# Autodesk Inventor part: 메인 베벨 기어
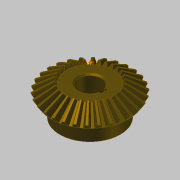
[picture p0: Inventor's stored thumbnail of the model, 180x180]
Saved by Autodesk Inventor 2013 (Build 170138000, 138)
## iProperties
Created: 2016-04
Part Number: 메인 베벨 기어
Material: 강철, 탄소
Document SubType Name: Modeling
Designer: mdu
Categories: <?xml version="1.0" encoding="UTF-16"?> <MemberInstance><Categories><FamilyTemplate><FamilyTemplateParameter ValueType="xs:double" Id="1" ObjectReferenceKey="da
Mass: 269.926 g
Surface Area: 108.837 cm^2
Volume: 34.2981 cm^3
Density: 7.87 g/cm^3
CustomPartVersion: 1
Author: mdu
Revision Number: 1
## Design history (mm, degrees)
node "맨 위 점"
node "메쉬 평면2"
sketch "톱니 본체 스케치"
  geometry: L1 (0, 0)-(28.669, -21.997); L2 (28.669, -21.997)-(31.109, -18.336); L3 (31.109, -18.336)-(0, 0); L4 (30, -20)-(0, 0); L5 (17.219, -13.212)-(18.685, -11.013); L6 (28.669, -21.997)-(17.219, -13.212); L7 (31.109, -18.336)-(18.685, -11.013); L8 (0, -39.387)-(0, 6.564) reference; L9 (0, -20)-(31.109, -20)
  constraints: 16 end point, 4 point on line, 3 perpendicular, 2 collinear, 1 horizontal alignment, 1 vertical alignment
  dimensions: "d0" = 60 diameter of L4.start L8 (= da_de); "d1" = 57.33744 diameter of L1.end L8 (= da_dfe); "d2" = 62.2188 diameter of L2.end L8 (= da_dae); "d3" = 14.4 distance between parallel lines of L2 L5 (= da_b); "d4" = 18.3359 vertical distance of L2.end L1.start (= da_ve)
revolve "톱니 본체" sketch "톱니 본체 스케치" stored, may be unused: angle "d5" = 90 deg
node "시작점"
node "톱니 평면"
sketch "시작 스케치"
  geometry: L1 (0, -23.505)-(0, 10.645) reference; L2 (-0.709, -2.928)-(0.709, -2.928); A1 r 19.188 centre (-19.457, -7.014) between (-0.709, -2.928) and (-3.232, 3.229); A2 r 19.188 centre (19.457, -7.014) between (3.232, 3.229) and (0.709, -2.928); A3 r 57.403 centre (0, -54.083) between (3.232, 3.229) and (-3.232, 3.229); 1 further point
  constraints: 6 point on circle, 3 centre point, 3 symmetric about line, 2 end point, 1 coincident, 1 perpendicular, 1 other
  dimensions: "d7" = 19.18795 radius of A1 (= fd_rr); "d8" = 19.45712 horizontal distance of point (0, -54.083) A1.centre (= fd_x); "d9" = 47.06905 vertical distance of point (0, -54.083) A1.centre (= fd_y); "d57" = 57.40327 radius of A3 (= 0.5 x fd_dva + 0.3 x da_he); "d58" = 51.15527 distance from line of A3.centre L2 (= 0.5 x fd_dva - 1.12 x da_he)
node "끝점"
  node "끝 평면"
sketch "3D 스케치 오른쪽"
  node "Helical Curve Right" dims "d65" = 229.90621 (computed from da_dm, da_delta, da_beta), "d66" = 31.5, "d67" = 60 (= da_de), "d68" = -9.82794 (= -da_delta), "d69" = 8.10972 (computed from fd_loft, da_delta)
node "끝 평면 오른쪽"
sketch "끝 스케치 오른쪽"
  geometry: L1 (0, -41.54)-(0, 13.178) reference; L2 (-0.422, -1.69)-(0.422, -1.69); A1 r 11.427 centre (-11.587, -4.123) between (-0.422, -1.69) and (-1.925, 1.977); A2 r 11.427 centre (11.587, -4.123) between (1.925, 1.977) and (0.422, -1.69); A3 r 34.184 centre (0, -32.153) between (1.925, 1.977) and (-1.925, 1.977); 1 further point
  constraints: 6 point on circle, 3 centre point, 3 symmetric about line, 2 end point, 1 coincident, 1 perpendicular, 1 other
  dimensions: "d70" = 11.58699 horizontal distance of A3.centre A1.centre (computed from fd_x, fd_ratio); "d71" = 28.03028 vertical distance of point (0, -32.153) A1.centre (computed from fd_y, fd_ratio); "d72" = 11.4267 radius of A1 (computed from fd_rr, fd_ratio); "d73" = 30.46369 distance from line of point (0, -32.153) L2 (computed from d58, fd_ratio); "d74" = 34.18446 radius of A3 (computed from d57, fd_ratio)
feature "로프트 오른쪽" sketch "끝 스케치 오른쪽" dims "d75" = 0, "d77" = 0, "d79" = 0, "d80" = 90 deg, "d85" = 20, "d92" = 90 deg, "d93" = 90 deg, "da_teethtype" = 0 [user parameter]
sketch "3D 스케치 왼쪽"
  node "Helical Curve Left" dims "d26" = 229.90621 (computed from da_dm, da_delta, da_beta), "d27" = 8.10972 (computed from fd_loft, da_delta), "d28" = 60 (= da_de), "d29" = -9.82794 (= -da_delta)
node "끝 평면 왼쪽"
sketch "끝 스케치 왼쪽" dims "d56" = 10.3728 (derived)
  geometry: L1 (0, -43.753)-(0, 15.405) reference; L2 (-0.422, -1.678)-(0.422, -1.678); A1 r 11.427 centre (-11.587, -4.111) between (-0.422, -1.678) and (-1.925, 1.988); A2 r 11.427 centre (11.587, -4.111) between (1.925, 1.988) and (0.422, -1.678); A3 r 34.184 centre (0, -32.142) between (1.925, 1.988) and (-1.925, 1.988); 2 further points; 1 other entity
  constraints: 6 point on circle, 3 centre point, 3 symmetric about line, 2 end point, 1 coincident, 2 other
  dimensions: "d30" = 11.4267 radius of A1 (computed from fd_rr, fd_ratio); "d31" = 11.58699 horizontal distance of point (0, -32.142) A1.centre (computed from fd_x, fd_ratio); "d32" = 28.03028 vertical distance of A1.centre point (0, -32.142) (computed from fd_y, fd_ratio); "d61" = 34.18446 radius of A3 (computed from d57, fd_ratio); "d62" = 30.46369 distance from line of point (0, -32.142) L2 (computed from d58, fd_ratio)
feature "로프트 왼쪽" sketch "끝 스케치 왼쪽" dims "d35" = 0, "d37" = 0, "d39" = 0, "d40" = 90 deg, "d84" = 10, "d90" = 90 deg, "d91" = 90 deg, "da_teethtype" = 0 [user parameter]
sketch "본체 스케치"
  geometry: L1 (0, -35.038)-(0, -19.531) reference; L2 (28.669, -21.997)-(17.219, -13.212) reference; L3 (17.219, -13.212)-(0, -13.212); L4 (28.669, -21.997)-(0, -21.997)
  constraints: 4 end point, 2 perpendicular, 2 point on line
revolve "본체 고정" sketch "본체 스케치" stored, may be unused: angle "d46" = 90 deg
feature "피치 지름" dims angle "d47" = 90 deg
sketch "스케치8"
  geometry: C1 r 22.5 at (0, 0); 1 further point
  constraints: 1 centre point, 1 coincident
  dimensions: "d94" = 45 diameter of C1
extrude "돌출1" join sketch "스케치8" distance "d95" = 13; taper "d96" = 0 deg
sketch "스케치9"
  geometry: 1 further point
hole "구멍1" sketch "스케치9" at (0, 0) diameter "d97" = 17; stored, may be unused: countersink angle "d101" = 90 deg, drill point angle "d103" = 118 deg; dims "d98" = 6, "d99" = 4, "d100" = 2, "d102" = 8
sketch "스케치10"
  geometry: L1 (8.124, 2.5)-(10.8, 2.5); L2 (10.8, 2.5)-(10.8, -2.5); L3 (10.8, -2.5)-(8.124, -2.5); A1 r 8.5 centre (0, 0) between (8.124, 2.5) and (8.124, -2.5) reference; 1 further point
  constraints: 6 end point, 2 parallel, 2 point on circle, 1 horizontal, 1 perpendicular
  dimensions: "d104" = 5 distance of L1.end L2.end; "d112" = 19.3 dimension on A1 L2
extrude "돌출2" cut sketch "스케치10" stored distance "d106" = 10; taper "d107" = 0 deg
chamfer "모따기1" distance "d108" = 1; stored, may be unused: second distance "d109" = 2, angle "d110" = 45 deg
fillet "모깎기1" dims "d111" = 2
body "Solid1"
feature "로프트" dims "d17" = 0, "d18" = 90 deg, "d19" = 0, "d20" = 90 deg, "d89" = 0, "da_teethtype" = 0 [user parameter]
pattern_circular "원형 패턴" dims angle "d22" = 360 deg, "d88" = 0, "da_teethtype" = 0 [user parameter]
pattern_circular "원형 패턴 오른쪽" dims angle "d82" = 360 deg, "da_teethtype" = 0 [user parameter]
pattern_circular "원형 패턴 왼쪽" dims angle "d42" = 360 deg, "da_teethtype" = 0 [user parameter]
sketch "끝 스케치"
  geometry: L1 (0, -15.359)-(0, 6.983) reference; L2 (-0.422, -1.69)-(0.422, -1.69); A1 r 11.427 centre (-11.587, -4.123) between (-0.422, -1.69) and (-1.925, 1.977); A2 r 11.427 centre (11.587, -4.123) between (1.925, 1.977) and (0.422, -1.69); A3 r 34.184 centre (0, -32.153) between (1.925, 1.977) and (-1.925, 1.977); 1 further point
  constraints: 6 point on circle, 3 centre point, 3 symmetric about line, 2 end point, 1 coincident, 1 other
  dimensions: "d12" = 11.4267 radius of A1 (computed from fd_rr, fd_ratio); "d15" = 11.58699 horizontal distance of A1.centre point (0, -32.153) (computed from fd_x, fd_ratio); "d16" = 28.03028 vertical distance of A1.centre point (0, -32.153) (computed from fd_y, fd_ratio); "d59" = 34.18446 radius of A3 (computed from d57, fd_ratio); "d60" = 30.46369 distance from line of A3.centre L2 (computed from d58, fd_ratio)
sketch "Sketch6"
  geometry: L1 (30, -20)-(0, 0) reference; L2 (0, -37.8)-(0, 6.3) reference
body "Srf1"
other parameters: "da_b" = 14.4 [user parameter; used in 2 equation terms], "da_de" = 60 [user parameter; used in 4 equation terms], "da_dae" = 62.2188 [user parameter; used in 2 equation terms], "da_dfe" = 57.33744 [user parameter; used in 1 equation term], "da_le" = 36.05551 [user parameter; used in 1 equation term], "da_omega" = 90 deg [user parameter; used in 1 equation term], "da_beta" = 0 [user parameter; used in 2 equation terms], "da_delta" = 9.82794 [user parameter; used in 8 equation terms], "da_alpha" = 20 deg [user parameter; used in 2 equation terms], "da_he" = 4.4 [user parameter; used in 4 equation terms], "da_ve" = 18.3359 [user parameter; used in 1 equation term], "fd_dv" = 108.16654 (computed from da_de, da_delta) [user parameter; used in 1 equation term], "fd_dva" = 112.16654 (computed from da_dae, da_delta) [user parameter; used in 3 equation terms], "fd_dvb" = 101.6433 (computed from fd_dv, da_alpha) [user parameter; used in 2 equation terms], "da_zv" = 540.83269 [user parameter; used in 1 equation term], "fd_loft" = 14.62 (= da_b + 0.05 x da_he) [user parameter; used in 4 equation terms], "fd_ratio" = 5.95514 (computed from da_le, fd_loft) [user parameter; used in 15 equation terms], "fd_rr" = 19.18795 (computed from fd_dd, fd_dvb) [user parameter; used in 6 equation terms], "fd_angle" = 0.29367 (computed from da_zv) [user parameter; used in 4 equation terms], "fd_x1" = 1.58802 (computed from da_dvw, fd_angle) [user parameter; used in 1 equation term], "fd_y1" = 54.05995 (computed from da_dvw, fd_angle) [user parameter; used in 1 equation term], "fd_x2" = 17.8691 (computed from fd_rr, fd_angle2, fd_angle) [user parameter; used in 1 equation term], "fd_y2" = 6.9909 (computed from fd_rr, fd_angle2, fd_angle) [user parameter; used in 1 equation term], "fd_x" = 19.45712 (= fd_x1 + fd_x2) [user parameter; used in 4 equation terms], "fd_y" = 47.06905 (= fd_y1 - fd_y2) [user parameter; used in 4 equation terms], "fd_angle2" = 3.43555 (computed from fd_dvb, fd_dd, da_alpha) [user parameter; used in 2 equation terms], "fd_dd" = 108.64654 (= fd_dva - 0.8 x da_he) [user parameter; used in 2 equation terms], "da_dvw" = 108.16654 [user parameter; used in 2 equation terms], "d11" = 14.62 (= fd_loft), "da_dm" = 48.01848 [user parameter; used in 2 equation terms], "da_x" = 0 [user parameter], "da_m" = 2 [user parameter], "d48" = 0, "d49" = 0, "d50" = 90 deg (= da_omega), "d51" = 6 deg (computed from da_z), "d52" = 0, "d53" = 0, "d54" = 0
